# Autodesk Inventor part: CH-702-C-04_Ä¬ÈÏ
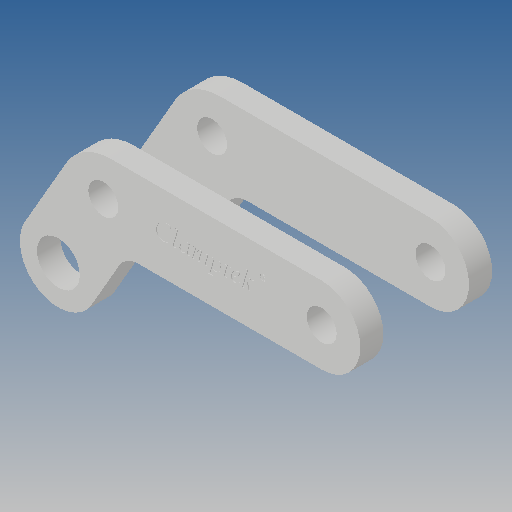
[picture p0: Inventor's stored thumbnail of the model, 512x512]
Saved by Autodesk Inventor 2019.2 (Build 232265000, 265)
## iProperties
Created: 2010-06
Part Number: CH-702-C-04_Ä¬ÈÏ
Material: Ogólny
Document SubType Name: Modeling
Designer: CADENGINEERING4
Density: 1 g/cm^3
Appearance: Domyślna
Author: CADENGINEERING4
Revision Number: ÈÎºÎ
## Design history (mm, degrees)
feature "NONE"
feature "NONE:1"
node "Bryła1"
node "Bryła2"
